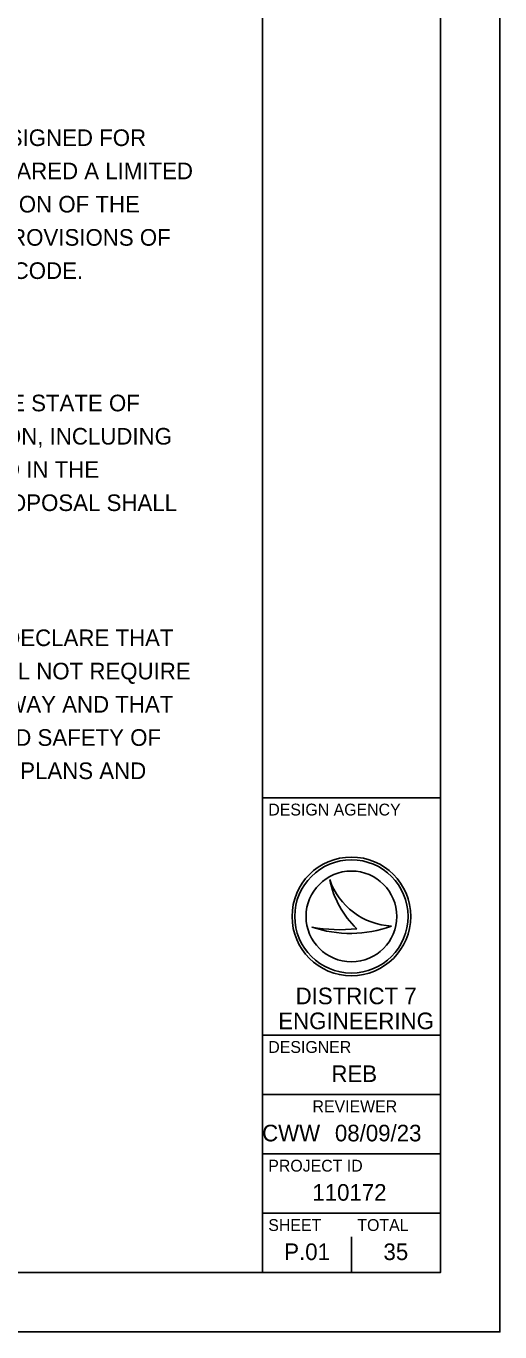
# Model space of a CAD drawing. Extents: x 0 to 34, y 0 to 22.
# Drawn here: x 30.01 to 34, y 0 to 11 of the extents above; entities that cross this region are included whole.
import ezdxf

# ---------------------------------------------------------------- set-up
doc = ezdxf.new("R2010")
doc.units = 0
for name, color, linetype in [('SH_Border', 7, 'Continuous'), ('SH_Cut_Line', 7, 'Continuous'), ('SH_Data', 7, 'Continuous'), ('SH_Text', 7, 'Continuous')]:
    doc.layers.add(name, color=color, linetype=linetype)

msp = doc.modelspace()

# ---------------------------------------------------------------- linework, layer by layer
at = {"layer": 'SH_Border'}
for p, q in [((32, 0.5), (32, 21.5)), ((32, 4.5), (33.5, 4.5)), ((32, 2.5), (33.5, 2.5)), ((32, 2), (33.5, 2)), ((32, 1.5), (33.5, 1.5)), ((32, 1), (33.5, 1))]:
    msp.add_line(p, q, dxfattribs=at)
msp.add_lwpolyline([(1.5, 21.5), (33.5, 21.5), (33.5, 0.5), (1.5, 0.5)], close=True, dxfattribs=at)
at = {"layer": 'SH_Cut_Line'}
msp.add_lwpolyline([(0, 0), (34, 0), (34, 22), (0, 22)], close=True, dxfattribs=at)
at = {"layer": 'SH_Data'}
for p, q in [((32.567, 3.81), (32.567, 3.81)), ((32.75, 3.5), (32.75, 3.5)), ((33.087, 3.419), (33.087, 3.419)), ((32.417, 3.41), (32.417, 3.41)), ((32.75, 0.5), (32.75, 0.8)), ((32.375, 0.675), (32.375, 0.675))]:
    msp.add_line(p, q, dxfattribs=at)
for radius in [0.5, 0.477, 0.477, 0.382]:
    msp.add_circle((32.75, 3.5), radius, dxfattribs=at)
for centre, radius, start, end in [((33.116, 3.998), 0.58, 198.9257, 198.9319), ((33.347, 3.97), 0.796, 191.6379, 191.6421), ((33.116, 3.998), 0.58, 198.9319, 267.1657), ((33.347, 3.97), 0.796, 191.6421, 226.0947), ((32.739, 4.37), 1.013, 251.4576, 290.0832), ((32.648, 4.654), 1.266, 259.4964, 259.4995), ((32.739, 4.37), 1.013, 251.4527, 251.4576), ((32.648, 4.654), 1.266, 259.4995, 276.6672)]:
    msp.add_arc(centre, radius, start, end, dxfattribs=at)

# ---------------------------------------------------------------- texts
for s, height, p in [('I HEREBY APPROVE THESE PLANS AND DECLARE THAT', 0.14, (26.154, 5.777)), ('THE MAKING OF THIS IMPROVEMENT WILL NOT REQUIRE', 0.14, (26.154, 5.497)), ('THE CLOSING TO TRAFFIC OF THE HIGHWAY AND THAT', 0.14, (26.154, 5.217)), ('PROVISIONS FOR THE MAINTENANCE AND SAFETY OF', 0.14, (26.154, 4.937)), ('TRAFFIC WILL BE AS SET FORTH ON THE PLANS AND', 0.14, (26.154, 4.657)), ('DESIGN AGENCY', 0.1, (32.05, 4.35)), ('DESIGNER', 0.1, (32.05, 2.35)), ('REB', 0.14, (32.581, 2.105)), ('REVIEWER', 0.1, (32.422, 1.85)), ('CWW', 0.14, (31.998, 1.605)), ('08/09/23', 0.14, (32.611, 1.605)), ('PROJECT ID', 0.1, (32.05, 1.35)), ('110172', 0.14, (32.421, 1.105)), ('SHEET', 0.1, (32.05, 0.85)), ('TOTAL', 0.1, (32.8, 0.85)), ('P.01', 0.14, (32.184, 0.605)), ('35', 0.14, (33.02, 0.605))]:
    msp.add_text(s, height=height, dxfattribs=at).set_placement(p)
at = {"layer": 'SH_Text'}
for s, p in [('  THIS IMPROVEMENT IS ESPECIALLY DESIGNED FOR', (26.142, 9.99)), ('THROUGH TRAFFIC AND HAS BEEN DECLARED A LIMITED', (26.142, 9.71)), ('ACCESS HIGHWAY OR FREEWAY BY ACTION OF THE', (26.142, 9.43)), ('DIRECTOR IN ACCORDANCE WITH THE PROVISIONS OF', (26.142, 9.15)), ('SECTION 5511.02 OF THE OHIO REVISED CODE.', (26.142, 8.87)), (' THE STANDARD SPECIFICATIONS OF THE STATE OF', (26.142, 7.755)), ('OHIO, DEPARTMENT OF TRANSPORTATION, INCLUDING', (26.142, 7.475)), ('SUPPLEMENTAL SPECIFICATIONS LISTED IN THE', (26.142, 7.195)), ('PLANS AND CHANGES LISTED IN THE PROPOSAL SHALL', (26.142, 6.915)), ('DISTRICT 7', (32.28, 2.76)), ('ENGINEERING', (32.134, 2.55))]:
    msp.add_text(s, height=0.14, dxfattribs=at).set_placement(p)

doc.saveas('drawing.dxf')
